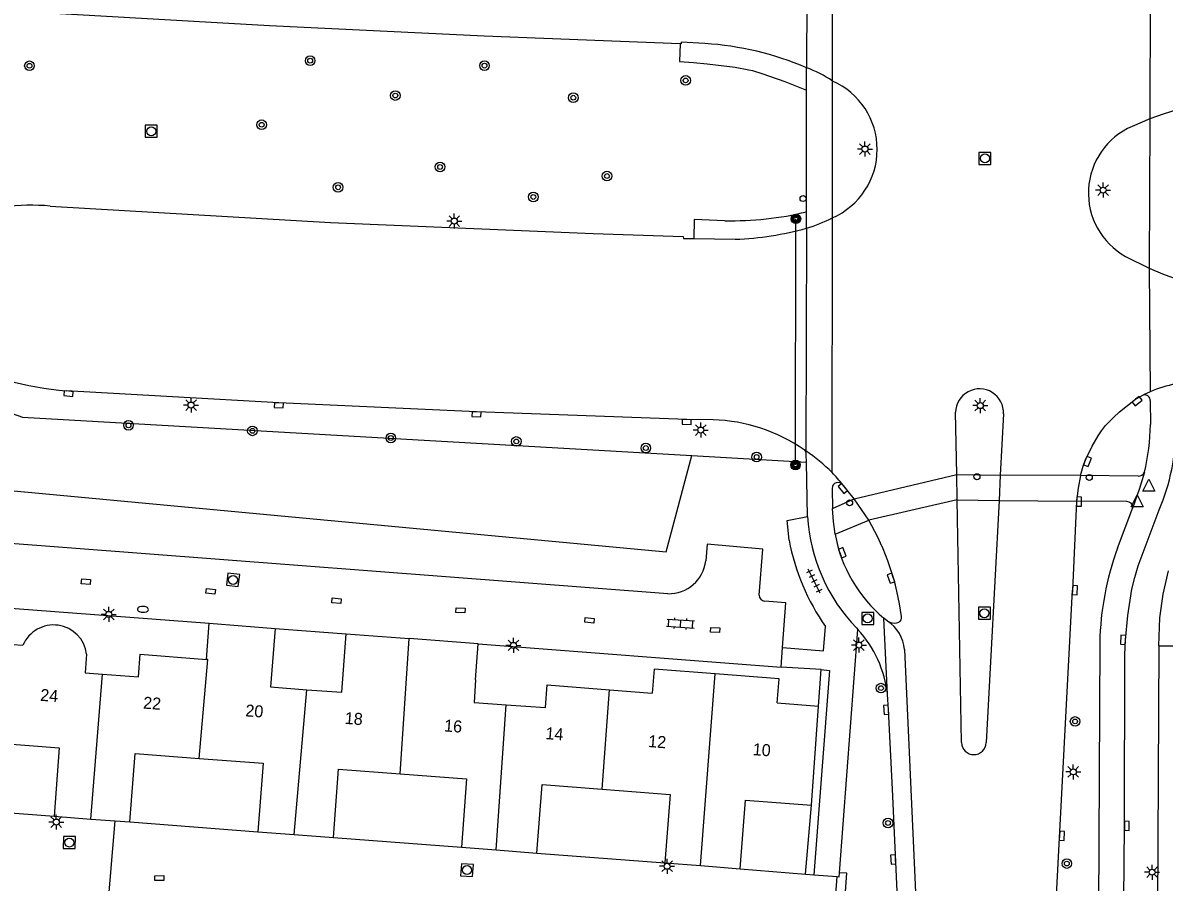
# Model space of a CAD drawing. Extents: x 132999 to 136000, y 398499 to 400501.
# Drawn here: x 134071.6 to 134166.7, y 399130.5 to 399202.1 of the extents above; entities that cross this region are included whole.
import ezdxf

# ---------------------------------------------------------------- set-up
doc = ezdxf.new("R2010")
doc.units = 0
for name, color, linetype in [('gg-afsc-hekwerk', 7, 'Continuous'), ('gg-afsc-muur', 7, 'Continuous'), ('gg-anno-huisnummerreeks BGT', 7, 'Continuous'), ('gg-bbg-hoofdgebouw', 7, 'Continuous'), ('gg-bbg-tussenscheiding', 7, 'Continuous'), ('gg-knt-verharding', 7, 'Continuous'), ('gg-knt-verharding nz', 7, 'Continuous'), ('gt-grn-groengrens', 7, 'Continuous'), ('gt-grn-weggrens', 7, 'Continuous'), ('gt-knt-lijn portaal', 7, 'Continuous'), ('gt-symb-boom', 7, 'Continuous'), ('gt-symb-brandkraan', 7, 'Continuous'), ('gt-symb-drukknoppaal', 7, 'Continuous'), ('gt-symb-klinker verharding', 7, 'Continuous'), ('gt-symb-kolk', 7, 'Continuous'), ('gt-symb-kolk center center', 7, 'Continuous'), ('gt-symb-lichtmast', 7, 'Continuous'), ('gt-symb-portaalmast', 7, 'Continuous'), ('gt-symb-rioolschacht', 7, 'Continuous'), ('gt-symb-tegel verharding', 7, 'Continuous'), ('gt-symb-verkeersregelinstallatiepaal', 7, 'Continuous'), ('gt-symb-waterafsluiter', 7, 'Continuous')]:
    doc.layers.add(name, color=color, linetype=linetype)

# ---------------------------------------------------------------- blocks, each defined once
blk = doc.blocks.new('gt0-BOOM')
at = {"layer": 'gt-symb-boom'}
for radius in [0.4, 0.2]:
    blk.add_circle((0, 0), radius, dxfattribs=at)
blk = doc.blocks.new('gt0-RS')
at = {"layer": 'gt-symb-rioolschacht'}
blk.add_lwpolyline([(-0.5, -0.5), (0.5, -0.5), (0.5, 0.5), (-0.5, 0.5)], close=True, dxfattribs=at)
blk.add_circle((0, 0), 0.375, dxfattribs=at)
blk = doc.blocks.new('gt0-PORTM')
at = {"layer": 'gt-symb-portaalmast'}
for radius in [0.4, 0.33, 0.27, 0.21, 0.15]:
    blk.add_circle((0, 0), radius, dxfattribs=at)
blk = doc.blocks.new('gt0-DPAAL')
at = {"layer": 'gt-symb-drukknoppaal'}
blk.add_circle((0, 0), 0.25, dxfattribs=at)
blk = doc.blocks.new('gt0-KOLK')
at = {"layer": 'gt-symb-kolk'}
blk.add_lwpolyline([(0, 0), (0.375, 0), (0.375, 0.4), (-0.375, 0.4), (-0.375, 0), (0, 0)], dxfattribs=at)
blk = doc.blocks.new('gt0-LMAST')
at = {"layer": 'gt-symb-lichtmast'}
for p, q in [((-0.182, 0.173), (-0.447, 0.438)), ((-0.005, 0.246), (-0.005, 0.621)), ((0.172, 0.173), (0.437, 0.438)), ((-0.255, -0.004), (-0.63, -0.004)), ((-0.182, -0.181), (-0.447, -0.446)), ((-0.005, -0.254), (-0.005, -0.629)), ((0.437, -0.446), (0.172, -0.181)), ((0.245, -0.004), (0.62, -0.004))]:
    blk.add_line(p, q, dxfattribs=at)
blk.add_circle((-0.005, -0.004), 0.25, dxfattribs=at)
blk = doc.blocks.new('gt0-TEG1')
at = {"layer": 'gt-symb-tegel verharding'}
for p, q in [((-1.125, 0), (1.125, 0)), ((-0.9, -0.25), (-0.9, 0.25)), ((-0.45, -0.25), (-0.45, 0.25)), ((0, -0.25), (0, 0.25)), ((0.45, -0.25), (0.45, 0.25)), ((0.9, -0.25), (0.9, 0.25))]:
    blk.add_line(p, q, dxfattribs=at)
blk = doc.blocks.new('gt0-KOLKCC')
at = {"layer": 'gt-symb-kolk center center'}
blk.add_lwpolyline([(-0.375, 0.2), (0.375, 0.2), (0.375, -0.2), (-0.375, -0.2)], close=True, dxfattribs=at)
blk = doc.blocks.new('gt0-BR')
at = {"layer": 'gt-symb-brandkraan'}
for centre, radius, start, end in [((-0.244, 0), 0.206, 107.56694, 252.43307), ((0.599, -2.664), 3, 106.89205, 107.56694), ((0, -0.691), 0.938, 73.10799, 106.89205), ((-0.599, -2.664), 3, 72.43309, 73.10799), ((0.244, 0), 0.206, 287.56695, 72.43309), ((0.599, 2.664), 3, 252.43307, 253.10797), ((0, 0.691), 0.938, 253.10797, 286.89206), ((-0.599, 2.664), 3, 286.89206, 287.56695)]:
    blk.add_arc(centre, radius, start, end, dxfattribs=at)
blk = doc.blocks.new('gt0-KL1')
at = {"layer": 'gt-symb-klinker verharding'}
for p, q in [((-1.15, 0.3), (1.15, 0.3)), ((-1, -0.3), (-1, 0.3)), ((-0.5, 0.3), (-0.5, 0.45)), ((0, -0.3), (0, 0.3)), ((0.5, 0.3), (0.5, 0.45)), ((1, -0.3), (1, 0.3)), ((-1.15, -0.3), (1.15, -0.3)), ((-0.5, -0.45), (-0.5, -0.3)), ((0.5, -0.45), (0.5, -0.3))]:
    blk.add_line(p, q, dxfattribs=at)
blk = doc.blocks.new('gt0-WAFSL')
at = {"layer": 'gt-symb-waterafsluiter'}
for p, q in [((-0.5, -0.333), (0, 0.667)), ((0, 0.667), (0.5, -0.333)), ((0.5, -0.333), (-0.5, -0.333))]:
    blk.add_line(p, q, dxfattribs=at)
blk = doc.blocks.new('gt0-VIPAAL')
at = {"layer": 'gt-symb-verkeersregelinstallatiepaal'}
blk.add_circle((0, 0), 0.25, dxfattribs=at)

msp = doc.modelspace()

# ---------------------------------------------------------------- linework, layer by layer
at = {"layer": 'gg-afsc-hekwerk'}
msp.add_line((134137.881, 399145.19), (134138.104, 399148.228), dxfattribs=at)
at = {"layer": 'gg-afsc-muur'}
for p, q in [((134063.561, 399136.82), (134074.211, 399136.01)), ((134136.787, 399131.175), (134137.281, 399136.94)), ((134080.521, 399135.53), (134091.191, 399134.71)), ((134097.481, 399134.24), (134108.141, 399133.43)), ((134114.411, 399132.94), (134125.071, 399132.12)), ((134131.361, 399131.64), (134136.787, 399131.175))]:
    msp.add_line(p, q, dxfattribs=at)
at = {"layer": 'gg-bbg-hoofdgebouw'}
for p, q in [((134086.909, 399149.07), (134087.144, 399152.084)), ((134087.144, 399152.084), (134092.621, 399151.657)), ((134092.621, 399151.657), (134092.241, 399146.78)), ((134069.894, 399150.379), (134071.626, 399150.251)), ((134098.311, 399148.21), (134098.533, 399151.197)), ((134098.533, 399151.197), (134103.793, 399150.805)), ((134109.529, 399150.378), (134103.793, 399150.805)), ((134109.321, 399147.37), (134109.529, 399150.378)), ((134081.391, 399149.5), (134086.909, 399149.07)), ((134092.241, 399146.78), (134095.275, 399146.55)), ((134120.467, 399146.539), (134124.022, 399146.264)), ((134134.441, 399145.45), (134137.881, 399145.19)), ((134137.281, 399136.94), (134137.881, 399145.19)), ((134074.211, 399136.01), (134077.28, 399135.777)), ((134077.28, 399135.777), (134079.292, 399135.624)), ((134079.292, 399135.624), (134080.521, 399135.53)), ((134091.191, 399134.71), (134094.223, 399134.483)), ((134094.223, 399134.483), (134097.481, 399134.24)), ((134108.141, 399133.43), (134111.035, 399133.204)), ((134111.035, 399133.204), (134114.411, 399132.94)), ((134125.071, 399132.12), (134128.036, 399131.894)), ((134128.036, 399131.894), (134131.361, 399131.64))]:
    msp.add_line(p, q, dxfattribs=at)
for points in [[(134076.924, 399149.511), (134076.801, 399147.963), (134078.259, 399147.85)], [(134078.259, 399147.85), (134081.241, 399147.62), (134081.391, 399149.5)], [(134095.275, 399146.55), (134098.171, 399146.33), (134098.311, 399148.21)], [(134129.262, 399147.863), (134124.177, 399148.257), (134124.022, 399146.264)], [(134134.441, 399145.45), (134134.596, 399147.45), (134129.262, 399147.863)], [(134109.321, 399147.37), (134109.191, 399145.49), (134111.858, 399145.301)], [(134111.858, 399145.301), (134115.131, 399145.07), (134115.271, 399146.94), (134120.467, 399146.539)], [(134069.247, 399142.111), (134074.651, 399141.7), (134074.211, 399136.01)], [(134080.521, 399135.53), (134080.961, 399141.23), (134086.299, 399140.824)], [(134086.299, 399140.824), (134091.621, 399140.42), (134091.191, 399134.71)], [(134097.481, 399134.24), (134097.911, 399139.94), (134103.038, 399139.55)], [(134103.038, 399139.55), (134108.571, 399139.13), (134108.141, 399133.43)], [(134114.411, 399132.94), (134114.851, 399138.64), (134119.861, 399138.255)], [(134119.861, 399138.255), (134125.511, 399137.82), (134125.071, 399132.12)], [(134131.361, 399131.64), (134131.791, 399137.34), (134137.281, 399136.94)]]:
    msp.add_lwpolyline(points, dxfattribs=at)
msp.add_arc((134074.176, 399149.172), 2.769, 7.03893, 157.05833, dxfattribs=at)
at = {"layer": 'gg-bbg-tussenscheiding'}
for p, q in [((134103.038, 399139.55), (134103.793, 399150.805)), ((134077.28, 399135.777), (134078.259, 399147.85)), ((134128.036, 399131.894), (134129.262, 399147.863)), ((134094.223, 399134.483), (134095.275, 399146.55)), ((134119.861, 399138.255), (134120.467, 399146.539)), ((134111.035, 399133.204), (134111.858, 399145.301))]:
    msp.add_line(p, q, dxfattribs=at)
msp.add_lwpolyline([(134086.299, 399140.824), (134087.026, 399149.061), (134086.909, 399149.07)], dxfattribs=at)
at = {"layer": 'gg-knt-verharding'}
for p, q in [((134136.875, 399196.479), (134136.873, 399198.355)), ((134139.033, 399185.85), (134139.04, 399197.247)), ((134136.886, 399186.355), (134136.875, 399196.479)), ((134165.477, 399194.088), (134164.004, 399193.469)), ((134165.477, 399194.088), (134165.42, 399181.654)), ((134136.888, 399184.988), (134136.886, 399186.355)), ((134127.487, 399184.124), (134130.945, 399184.07)), ((134163.45, 399182.643), (134165.42, 399181.654)), ((134165.501, 399171.367), (134164.942, 399171.102)), ((134165.507, 399170.624), (134165.516, 399168.638)), ((134149.391, 399164.471), (134149.288, 399169.652)), ((134153.274, 399169.516), (134153.016, 399164.418)), ((134136.824, 399166.431), (134136.675, 399166.528)), ((134136.863, 399165.506), (134136.85, 399166.122)), ((134136.962, 399160.978), (134136.863, 399165.506)), ((134140.857, 399162.445), (134139.895, 399163.626)), ((134149.391, 399164.471), (134153.016, 399164.418)), ((134149.415, 399162.366), (134149.391, 399164.471)), ((134153.016, 399164.418), (134152.912, 399162.321)), ((134164.5, 399164.331), (134159.699, 399164.386)), ((134138.999, 399163.319), (134139.039, 399161.636)), ((134139.039, 399161.636), (134140.857, 399162.445)), ((134142.067, 399160.661), (134140.857, 399162.445)), ((134149.79, 399142.142), (134149.415, 399162.366)), ((134149.415, 399162.366), (134152.912, 399162.321)), ((134152.912, 399162.321), (134151.832, 399142.14)), ((134159.371, 399162.265), (134159.022, 399154.848)), ((134163.56, 399162.214), (134159.371, 399162.265)), ((134162.773, 399158.329), (134164.054, 399161.729)), ((134135.274, 399160.638), (134136.962, 399160.978)), ((134125.328, 399154.545), (134047.421, 399160.503)), ((134135.419, 399158.999), (134135.274, 399160.638)), ((134139.255, 399159.495), (134142.067, 399160.661)), ((134156.853, 399113.591), (134159.022, 399154.848)), ((134068.374, 399153.494), (134087.144, 399152.084)), ((134143.633, 399146.138), (134143.326, 399152.495)), ((134143.631, 399152.262), (134143.326, 399152.495)), ((134092.621, 399151.657), (134098.533, 399151.197)), ((134139.61, 399131.302), (134141.147, 399151.572)), ((134141.032, 399151.693), (134141.147, 399151.572)), ((134109.529, 399150.378), (134134.761, 399148.425)), ((134161.295, 399150.475), (134161.199, 399127.463)), ((134134.761, 399148.425), (134134.879, 399150.068)), ((134166.219, 399150.216), (134165.751, 399063.95)), ((134166.219, 399150.216), (134170.666, 399150.19)), ((134138.104, 399148.228), (134134.761, 399148.425)), ((134136.787, 399131.175), (134137.497, 399131.139)), ((134137.497, 399131.139), (134139.419, 399130.983)), ((134138.205, 399114.233), (134139.419, 399130.983))]:
    msp.add_line(p, q, dxfattribs=at)
for points in [[(134126.349, 399200.356), (134110.019, 399200.985), (134092.149, 399201.854), (134074.236, 399202.862), (134056.037, 399204.189), (134037.808, 399205.667), (134019.901, 399207.336), (134001.659, 399209.171), (133983.675, 399211.292), (133966.402, 399213.506), (133966.191, 399213.534)], [(134126.349, 399200.356), (134126.292, 399198.881), (134127.468, 399198.793), (134128.604, 399198.68), (134130.925, 399198.409), (134132.078, 399198.189), (134132.388, 399198.111), (134133.238, 399197.857), (134135.059, 399197.207), (134136.875, 399196.479)], [(134128.411, 399200.368), (134126.433, 399200.475), (134126.428, 399200.353), (134126.349, 399200.356)], [(134167.702, 399194.841), (134166.581, 399194.49), (134165.477, 399194.088)], [(134073.895, 399186.825), (134097.229, 399185.47), (134119.114, 399184.553), (134126.602, 399184.305), (134126.643, 399184.138), (134127.487, 399184.124)], [(134130.072, 399185.611), (134127.512, 399185.724), (134127.487, 399184.124)], [(134165.42, 399181.654), (134166.525, 399181.181), (134167.65, 399180.759)], [(134129.101, 399169.033), (134126.903, 399169.04), (134109.402, 399169.681), (134092.937, 399170.433), (134075.233, 399171.431)], [(134159.699, 399164.386), (134159.904, 399165.162), (134160.087, 399165.636), (134160.671, 399166.819), (134161.152, 399167.68), (134161.438, 399168.107), (134161.773, 399168.543), (134162.434, 399169.231), (134162.944, 399169.686), (134164.282, 399170.742), (134164.942, 399171.102)], [(134159.699, 399164.386), (134159.502, 399163.331), (134159.371, 399162.265)], [(134162.995, 399122.342), (134163.201, 399124.154), (134163.279, 399125.975), (134163.348, 399135.212), (134163.389, 399149.482), (134163.434, 399150.687), (134163.633, 399152.739), (134163.967, 399154.916), (134164.203, 399155.896), (134164.496, 399156.861), (134166.243, 399161.539)], [(134132.924, 399154.424), (134133.225, 399158.259), (134128.605, 399158.662), (134128.479, 399157.288)], [(134166.219, 399150.216), (134166.294, 399152.541), (134166.567, 399154.512), (134167.029, 399156.448)], [(134134.879, 399150.068), (134135.156, 399153.786), (134133.388, 399153.935)], [(134134.879, 399150.068), (134138.286, 399149.782), (134138.466, 399151.804)], [(134138.104, 399148.228), (134138.793, 399148.156), (134137.497, 399131.139)], [(134144.025, 399138.271), (134143.712, 399144.876), (134143.633, 399146.138)], [(134146.133, 399091.04), (134145.923, 399098.76), (134145.151, 399113.98), (134144.025, 399138.271)], [(134139.419, 399130.983), (134139.585, 399130.969), (134139.61, 399131.302)]]:
    msp.add_lwpolyline(points, dxfattribs=at)
for centre, radius, start, end in [((134126.818, 399174.878), 25.539, 66.81414, 86.42344), ((134133.678, 399189.434), 9.476, 55.5404, 70.29774), ((134136.539, 399191.55), 6.222, 293.62812, 66.3015), ((134166.391, 399187.92), 6.041, 113.27693, 240.86418), ((134072.339, 399171.012), 15.89, 84.37996, 112.37567), ((134130.626, 399212.11), 26.505, 268.80176, 283.66078), ((134132.729, 399198.437), 14.077, 287.18357, 296.60334), ((134129.994, 399209.923), 25.87, 272.10666, 285.45521), ((134078.815, 399205.958), 34.712, 247.46996, 264.0778), ((134151.282, 399169.616), 1.994, 357.13524, 178.95648), ((134169.326, 399162.57), 9.593, 100.23156, 113.49874), ((134165.023, 399170.625), 0.484, 359.93074, 99.60564), ((134128.625, 399154.89), 14.151, 55.32699, 88.07111), ((134147.423, 399168.895), 18.095, 346.46135, 359.18584), ((134150.529, 399168.289), 17.102, 336.75466, 0.34585), ((134136.358, 399166.151), 0.493, 356.68066, 49.95476), ((134129.325, 399155.134), 13.559, 44.47012, 56.42279), ((134129.351, 399155.165), 13.519, 38.74346, 44.45295), ((134164.527, 399164.858), 0.527, 267.11467, 337.87089), ((134139.505, 399163.303), 0.506, 39.58522, 178.24118), ((134163.561, 399161.721), 0.493, 0.98309, 90.07033), ((134151.569, 399161.846), 14.633, 183.40231, 223.93735), ((134123.311, 399149.84), 21.654, 7.46666, 29.98187), ((134153.601, 399162.456), 18.508, 190.76595, 215.13825), ((134150.934, 399161.603), 11.867, 190.23269, 230.12943), ((134185.9, 399149.911), 24.611, 159.99848, 178.68646), ((134125.427, 399157.612), 3.069, 268.14354, 353.93673), ((134133.411, 399154.422), 0.487, 179.72077, 267.27385), ((134144.193, 399153.129), 1.034, 237.03498, 280.22702), ((134144.327, 399152.571), 0.461, 276.17437, 10.42486), ((134133.997, 399145.015), 9.701, 6.64534, 42.52189), ((134150.811, 399142.159), 1.021, 180.96298, 358.92479)]:
    msp.add_arc(centre, radius, start, end, dxfattribs=at)
at = {"layer": 'gg-knt-verharding nz'}
for p, q in [((134165.516, 399213.018), (134165.477, 399194.088)), ((134165.42, 399181.654), (134165.501, 399171.367))]:
    msp.add_line(p, q, dxfattribs=at)
for points in [[(134165.015, 399164.659), (134164.581, 399163.231), (134164.054, 399161.729)], [(134139.255, 399159.495), (134139.113, 399160.56), (134139.039, 399161.636)], [(134145.043, 399149.893), (134147.698, 399091.082), (134146.133, 399091.04)]]:
    msp.add_lwpolyline(points, dxfattribs=at)
msp.add_arc((134141.876, 399149.611), 3.179, 5.09149, 56.5011, dxfattribs=at)
at = {"layer": 'gt-grn-groengrens'}
msp.add_line((134127.317, 399166.052), (134136.863, 399165.506), dxfattribs=at)
for points in [[(133988.636, 399180.799), (133988.747, 399175.977), (133991.314, 399174.773), (134033.95, 399170.552), (134043.82, 399165.641), (134125.192, 399158.027), (134127.317, 399166.052)], [(133988.636, 399180.799), (134053.07, 399174.231), (134062.021, 399172.628), (134071.589, 399169.238), (134127.317, 399166.052)], [(134136.191, 399075.386), (134140.241, 399131.256), (134139.61, 399131.302)]]:
    msp.add_lwpolyline(points, dxfattribs=at)
at = {"layer": 'gt-grn-weggrens'}
for p, q in [((134139.04, 399197.247), (134139.028, 399208.861)), ((134136.904, 399207.936), (134136.873, 399198.355)), ((134139.001, 399164.633), (134139.033, 399185.85)), ((134136.888, 399184.988), (134136.824, 399166.431)), ((134140.857, 399162.445), (134149.391, 399164.471)), ((134159.699, 399164.386), (134153.016, 399164.418)), ((134149.415, 399162.366), (134142.067, 399160.661)), ((134152.912, 399162.321), (134159.371, 399162.265)), ((134078.614, 399127.539), (134079.292, 399135.624))]:
    msp.add_line(p, q, dxfattribs=at)
at = {"layer": 'gt-knt-lijn portaal'}
msp.add_line((134135.956, 399165.268), (134135.991, 399185.767), dxfattribs=at)

# ---------------------------------------------------------------- block references
at = {"layer": 'gt-symb-boom'}
for p in [(134072.166, 399198.517), (134095.543, 399198.94), (134110.061, 399198.528), (134126.808, 399197.298), (134102.633, 399196.035), (134117.452, 399195.855), (134091.504, 399193.604), (134106.36, 399190.087), (134120.256, 399189.33), (134097.866, 399188.395), (134114.123, 399187.591), (134080.413, 399168.57), (134090.732, 399168.107), (134102.257, 399167.512), (134112.71, 399167.227), (134123.497, 399166.677), (134132.719, 399165.93), (134143.074, 399146.68), (134159.243, 399143.904), (134143.665, 399135.446), (134158.552, 399132.067)]:
    msp.add_blockref('gt0-BOOM', p, dxfattribs=at)
at = {"layer": 'gt-symb-brandkraan', "rotation": -2.7930955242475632}
msp.add_blockref('gt0-BR', (134081.617, 399153.243), dxfattribs=at)
at = {"layer": 'gt-symb-drukknoppaal'}
msp.add_blockref('gt0-DPAAL', (134136.584, 399187.456), dxfattribs=at)
at = {"layer": 'gt-symb-klinker verharding', "rotation": -3.669254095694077}
msp.add_blockref('gt0-KL1', (134126.393, 399152.057), dxfattribs=at)
at = {"layer": 'gt-symb-kolk'}
for p, rotation in [((134075.442, 399171.411), 173.43254780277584), ((134092.937, 399170.433), 176.8027123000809), ((134164.282, 399170.742), -141.70316939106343), ((134109.402, 399169.681), 177.38461339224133), ((134126.903, 399169.04), 177.90130518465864), ((134160.087, 399165.636), -111.14353802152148), ((134140.056, 399163.429), 129.1298690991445), ((134159.369, 399162.224), -90.90387307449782), ((134139.665, 399157.883), -68.43986286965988), ((134144.1, 399155.899), 108.46812529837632), ((134159.022, 399154.848), -93.01151504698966), ((134163.434, 399150.687), 86.61671238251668), ((134143.712, 399144.876), 93.60150340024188), ((134163.348, 399135.212), -90.40106390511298), ((134157.939, 399134.386), -92.97967378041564), ((134144.299, 399132.419), 92.69361103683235)]:
    msp.add_blockref('gt0-KOLK', p, dxfattribs=dict(at, rotation=rotation))
at = {"layer": 'gt-symb-kolk center center'}
for p, rotation in [((134076.873, 399155.549), 175.70279939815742), ((134087.252, 399154.74), 174.1151706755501), ((134097.742, 399153.958), 175.52454379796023), ((134108.06, 399153.159), 177.44910445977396), ((134118.801, 399152.325), 174.33357256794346), ((134129.264, 399151.521), 177.08561065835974), ((134082.977, 399130.855), -179.2090956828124)]:
    msp.add_blockref('gt0-KOLKCC', p, dxfattribs=dict(at, rotation=rotation))
at = {"layer": 'gt-symb-lichtmast'}
for p in [(134141.743, 399191.585), (134161.581, 399188.163), (134107.552, 399185.584), (134085.628, 399170.26), (134151.348, 399170.218), (134128.075, 399168.181), (134078.779, 399152.825), (134112.476, 399150.247), (134141.24, 399150.271), (134159.094, 399139.707), (134074.401, 399135.525), (134125.275, 399131.844), (134165.661, 399131.352)]:
    msp.add_blockref('gt0-LMAST', p, dxfattribs=at)
at = {"layer": 'gt-symb-portaalmast'}
for p in [(134135.991, 399185.767), (134135.956, 399165.268)]:
    msp.add_blockref('gt0-PORTM', p, dxfattribs=at)
at = {"layer": 'gt-symb-rioolschacht'}
for p in [(134082.307, 399193.059), (134151.729, 399190.804), (134151.685, 399152.917), (134141.974, 399152.482)]:
    msp.add_blockref('gt0-RS', p, dxfattribs=at)
for p, rotation in [((134089.123, 399155.695), -6.875783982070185), ((134075.492, 399133.82), -0.903873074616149), ((134108.603, 399131.52), -3.5773411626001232)]:
    msp.add_blockref('gt0-RS', p, dxfattribs=dict(at, rotation=rotation))
at = {"layer": 'gt-symb-tegel verharding', "rotation": 116.53943840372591}
msp.add_blockref('gt0-TEG1', (134137.512, 399155.59), dxfattribs=at)
at = {"layer": 'gt-symb-verkeersregelinstallatiepaal'}
for p in [(134151.068, 399164.285), (134160.425, 399164.227), (134140.465, 399162.116)]:
    msp.add_blockref('gt0-VIPAAL', p, dxfattribs=at)
at = {"layer": 'gt-symb-waterafsluiter'}
for p in [(134165.39, 399163.412), (134164.407, 399162.121)]:
    msp.add_blockref('gt0-WAFSL', p, dxfattribs=at)

# ---------------------------------------------------------------- texts
at = {"layer": 'gg-anno-huisnummerreeks BGT'}
for s, rotation, p in [('24', 355.7, (134073.038, 399145.627)), ('22', 355.7, (134081.604, 399144.978)), ('20', 355.7, (134090.119, 399144.333)), ('18', 355.7, (134098.401, 399143.705)), ('16', 355.7, (134106.674, 399143.078)), ('14', 355.7, (134115.112, 399142.438)), ('12', 355.6, (134123.665, 399141.777)), ('10', 355.6, (134132.372, 399141.103))]:
    msp.add_text(s, height=1, rotation=rotation, dxfattribs=at).set_placement(p)

doc.saveas('drawing.dxf')
